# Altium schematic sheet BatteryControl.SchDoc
size A
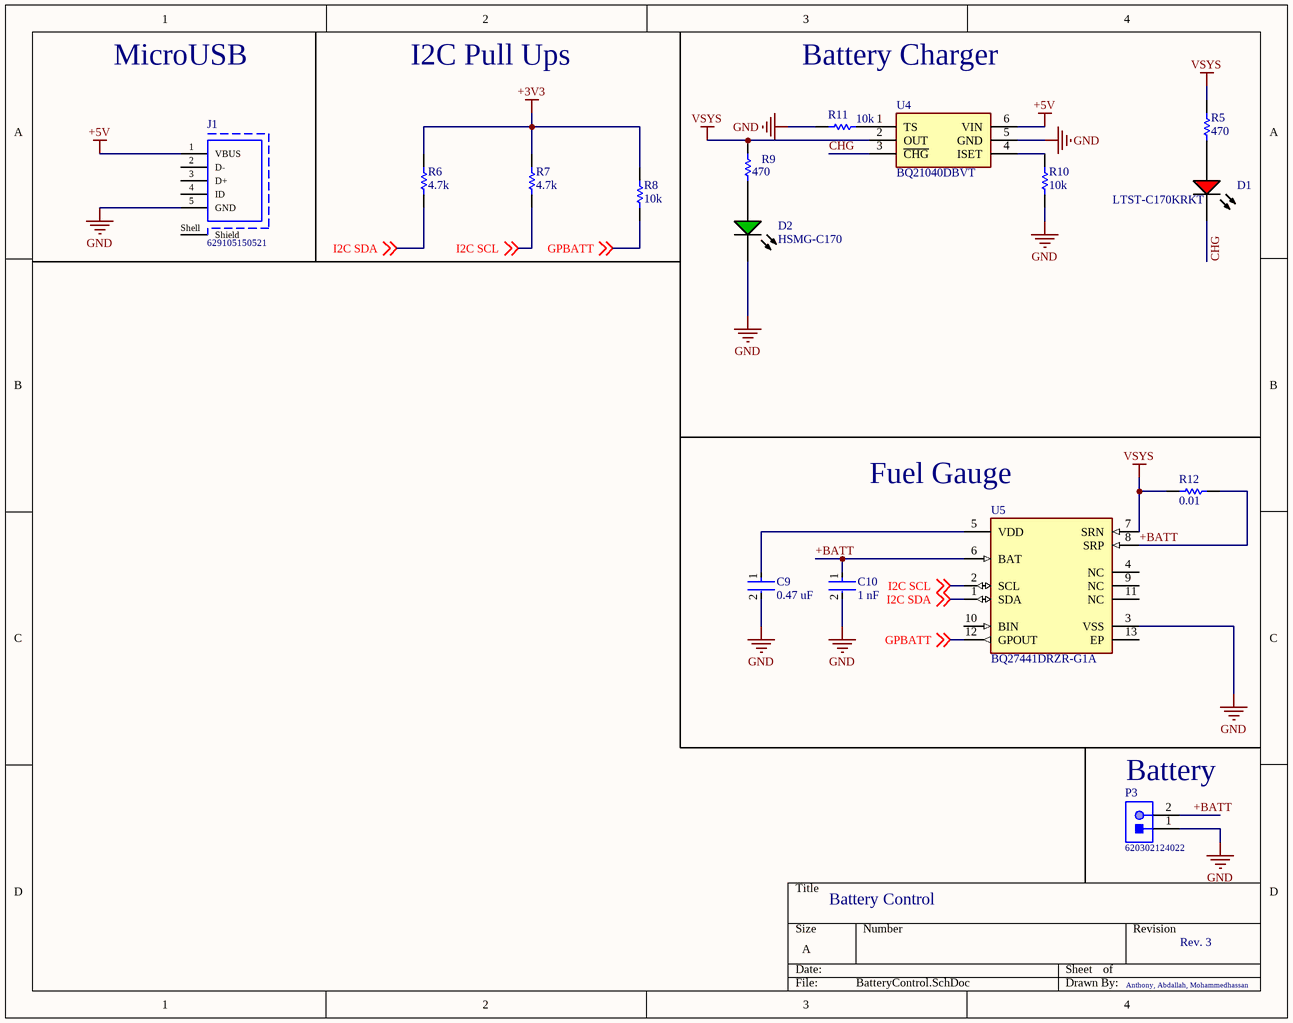
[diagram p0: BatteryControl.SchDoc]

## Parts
C9  0.47 uF  [FP-C0805C-DG-MFG]
C10  1 nF  [FP-C0805C-DG-MFG]
D1  LTST-C170KRKT  [LTST-C170KRKT_V]
D2  HSMG-C170  [AVAG-HSMX-C170_V]
J1  629105150521  [629105150521]
P3  620302124022  [620302124022]
R5  value 470  [RESC2013X70X40ML20T20]  (hidden comment: Resistor 1k +/-1% 0805 125 mW)
R6  value 4.7k  [RESC2013X70X40ML20T20]  (hidden comment: Resistor 1k +/-1% 0805 125 mW)
R7  value 4.7k  [RESC2013X70X40ML20T20]  (hidden comment: Resistor 1k +/-1% 0805 125 mW)
R8  value 10k  [RESC2013X70X40ML20T20]  (hidden comment: Resistor 1k +/-1% 0805 125 mW)
R9  value 470  [RESC2013X70X40ML20T20]  (hidden comment: Resistor 1k +/-1% 0805 125 mW)
R10  value 10k  [RESC2013X70X40ML20T20]  (hidden comment: Resistor 1k +/-1% 0805 125 mW)
R11  value 10k  [RESC2013X70X40ML20T20]  (hidden comment: Resistor 1k +/-1% 0805 125 mW)
R12  value 0.01  [RESC2013X70X40ML20T20]  (hidden comment: Resistor 1k +/-1% 0805 125 mW)
U4  BQ21040DBVT  [SOT95P280X145-6N]
U5  BQ27441DRZR-G1A  [FP-DRZ0012A-MFG]

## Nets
+3V3: R6.2 R7.2 R8.2
+5V: J1.1(VBUS) U4.6(VIN)
GND: C9.2 C10.2 D2.2(K) J1.5(GND) P3.1 R10.2 R11.2 U4.5(GND) U5.3(VSS)
VSYS: R5.2 R9.2 R12.2 U4.2(OUT) U5.7(SRN)
+BATT: C10.1 P3.2 R12.1 U5.6(BAT) U5.8(SRP)
CHG: D1.2(K) U4.3(~{CHG})
GPBATT: R8.1 U5.12(GPOUT) ; off-sheet GPBATT
I2C SCL: R7.1 U5.2(SCL) ; off-sheet I2C SCL
I2C SDA: R6.1 U5.1(SDA) ; off-sheet I2C SDA
NetC9_1: C9.1 U5.5(VDD)
NetD1_1: D1.1(A) R5.1
NetD2_1: D2.1(A) R9.1
NetR10_1: R10.1 U4.4(ISET)
NetR11_1: R11.1 U4.1(TS)

Not connected (* = marked no-connect by the designer): J1 2(D-) 3(D+) 4(ID) Shell(Shield); U5 4(NC) 9(NC) 10(BIN) 11(NC) 13(EP)

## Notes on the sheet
- MicroUSB
- I2C Pull Ups
- Battery Charger
- (near U5) Fuel Gauge
- (near P3) Battery
- Battery Control
- Rev. 3
- Anthony, Abdallah, Mohammedhassan

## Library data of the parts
C9 C10 = CMP-2007-03243-2: CAP CER 10UF 10V X5R 0805; Manufacturer Part Number: C0805C106K8PACTU; Manufacturer: Kemet; 3DS Part Number: 220-00001; Tolerance: 10%; Temperature Coefficient: 15%; Material: Ceramic
D1 = CMP-2000-07593-1: LED Red, 75 mW, 54 mcd, -55 to 85 degC, 2-Pin SMD, RoHS, Tape and Reel; Manufacturer: Lite-On; Lens Transparency: Clear; Number of Elements: 1; Power Rating: 75mW; Luminous Intensity: 54mcd; Viewing Angle: 130degrees; Forward Current: 30mA; Wavelength: 639nm; Lens Style: Rectangular; Case\/Package: 0805; Test Current: 20mA; Dominant Wavelength: 631nm; Forward Voltage: 2V; Lens Colour: Colorless
D2 = CMP-2000-05062-1: Chip LED, Green, 2.2 V, -40 to 85 degC, 2-Pin SMD, Pb-Free, Tape and Reel; Manufacturer: Avago; No. of Pins: 2; Peak Wavelength: 570nm; SVHC: NoSVHC(16-Jun-2014); Dominant Wavelength: 572nm; Forward Current If: 20mA; Viewing Angle: 170deg; Lens Shape: Rectangular; PIV Max: 5V; External Width: 1.25mm; LED Type: Standard; External Depth: 0.8mm; Opto Mounting Orientation: Top; Luminous Intensity: 15mcd; Luminous Intensity Min: 4mcd; Forward Voltage VF Max: 2.6V; External Length / Height: 2mm; Bulb Size: 1.25mmx1.4mm; Light Area Height: 1mm; Voltage Vf Typ: 2.2V
J1 = CMP-1502-03252-1: Micro USB 2.0 Type B Receptacle WR-COM, Horizontal, SMT, with Pegs, High Current at Pin 1 & Pin 5; Manufacturer: Wurth Elektronik; Contact Resistance: 30mOhm; Rated Current: 3A; Working Voltage: 30VAC
P3 = CMP-1502-00660-1: Male Shrouded Header WR-WTB, SMT, Vertical, pitch 2 mm, 1 x 2 position; Manufacturer: Wurth Elektronik; Pitch: 2mm; Position: 1x2; Working Voltage: 100VAC; Contact Resistance: 20mOhm
R5-R12 = CMP-009-00010-4: Chip Resistor, 1 KOhm, +/- 1%, 0.125 W, -55 to 155 degC, 0805 (2013 Metric); Power: 125mW; Voltage Rating: 150V
U4 = BQ21040DBVT: Integrated Circuit; Manufacturer_Name: Texas Instruments
U5 = CMP-04911-000008-1: IC BATT FUEL GAUGE LI-ION 12SON; Manufacturer: Texas Instruments; Number Of Cells: 1; Nominal Supply Current: 93uA; Max Supply Voltage: 4.5V; Standoff Height: 0mm; Min Supply Voltage: 2.45V; Output Voltage: 1.8V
